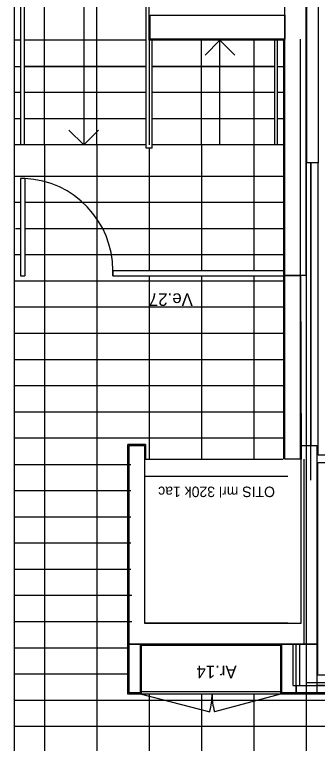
# Model space of a CAD drawing. Extents: x 1248 to 1356, y -443 to -224.
# Drawn here: x 1296.63 to 1299.52, y -237.59 to -230.63 of the extents above; entities that cross this region are included whole.
import ezdxf

# ---------------------------------------------------------------- set-up
doc = ezdxf.new("R2010")
doc.units = 0
for name, color, linetype in [('corte', 7, 'Continuous'), ('estereoctomias', 7, 'Continuous'), ('Level 1', 7, 'Continuous'), ('Level 10', 7, 'Continuous'), ('Level 13', 7, 'Continuous'), ('Level 2', 7, 'Continuous'), ('Level 3', 7, 'Continuous'), ('Level 40', 7, 'Continuous'), ('revestimentos', 7, 'Continuous'), ('vermelhos-cont', 7, 'Continuous')]:
    doc.layers.add(name, color=color, linetype=linetype)

msp = doc.modelspace()

# ---------------------------------------------------------------- linework, layer by layer
at = {"layer": 'corte'}
for p, q in [((1299.4204, -228.5639), (1299.4204, -232.0439)), ((1299.2133, -234.874), (1299.2133, -230.864)), ((1299.3633, -234.874), (1299.3633, -230.864)), ((1299.5304, -232.044), (1299.4204, -232.044)), ((1299.4604, -235.0752), (1299.4604, -232.044)), ((1297.834, -236.639), (1299.3933, -236.639)), ((1299.2908, -237.0363), (1299.9204, -237.0363)), ((1299.9904, -237.1063), (1299.1808, -237.1063)), ((1299.519, -237.1063), (1299.3208, -237.1063))]:
    msp.add_line(p, q, dxfattribs=at)
for points in [[(1299.4133, -233.1214), (1299.2133, -233.1214), (1299.2133, -228.5639), (1299.4133, -228.5639)], [(1299.519, -234.744), (1299.519, -236.639), (1297.724, -236.639), (1297.724, -234.744), (1297.874, -234.744), (1297.874, -236.439), (1299.369, -236.439), (1299.369, -234.744)]]:
    msp.add_lwpolyline(points, close=True, dxfattribs=at)
msp.add_lwpolyline([(1299.3208, -237.1063), (1299.3208, -236.639), (1299.519, -236.639), (1299.519, -237.1063)], dxfattribs=at)
at = {"layer": 'estereoctomias'}
for points in [[(1299.5304, -232.044), (1299.4204, -232.044), (1299.4204, -228.5639), (1299.2133, -228.5639), (1299.2133, -228.434), (1299.5304, -228.434)], [(1299.2133, -230.634), (1299.2133, -230.864), (1297.9283, -230.864), (1297.9283, -230.634)], [(1299.5304, -232.044), (1299.4604, -232.044), (1299.4604, -234.744), (1299.519, -234.744), (1299.519, -237.0059), (1299.9204, -237.0059), (1299.9204, -237.0363), (1299.519, -237.0363), (1299.519, -237.1047), (1299.519, -237.1063), (1299.9857, -237.1063), (1299.9904, -237.1063), (1299.9904, -236.9359), (1299.5297, -236.9359), (1299.5297, -234.9052), (1299.9329, -234.9052), (1299.9404, -234.9052), (1299.9404, -234.8352), (1299.5304, -234.8352)], [(1299.3633, -233.1214), (1299.369, -234.874), (1299.2133, -234.874), (1299.2133, -233.1214)], [(1297.834, -236.639), (1297.834, -237.1063), (1297.724, -237.1063), (1297.724, -236.639)], [(1299.2908, -236.639), (1299.2908, -237.0363), (1299.3208, -237.0363), (1299.3208, -237.1063), (1299.1808, -237.1063), (1299.1808, -236.639)]]:
    msp.add_lwpolyline(points, close=True, dxfattribs=at)
at = {"layer": 'Level 1'}
for p, q in [((1299.2133, -230.634), (1299.2133, -228.434)), ((1297.9283, -230.634), (1299.2133, -230.634)), ((1297.9283, -230.864), (1297.9283, -230.634)), ((1299.2133, -230.864), (1297.9283, -230.864)), ((1297.724, -234.744), (1297.724, -237.1063)), ((1297.8733, -234.744), (1297.7633, -234.744)), ((1299.369, -234.874), (1299.2133, -234.874)), ((1299.3933, -234.874), (1299.3933, -236.639)), ((1299.2433, -236.439), (1297.8733, -236.439)), ((1297.834, -237.1063), (1297.834, -236.639)), ((1299.1808, -236.639), (1299.1808, -237.1063)), ((1299.2908, -236.639), (1299.2908, -237.0363)), ((1299.3533, -236.639), (1299.3533, -237.0363)), ((1299.4204, -237.0059), (1299.9204, -237.0059)), ((1297.724, -237.1063), (1297.834, -237.1063))]:
    msp.add_line(p, q, dxfattribs=at)
at = {"layer": 'Level 10'}
for p, q in [((1296.9183, -231.874), (1296.9183, -230.124)), ((1297.4183, -231.874), (1297.4183, -230.124)), ((1296.6933, -230.874), (1296.6333, -230.874)), ((1297.8883, -230.874), (1296.7233, -230.874)), ((1298.4183, -231.874), (1298.4183, -230.874)), ((1298.9183, -230.874), (1298.9183, -231.874)), ((1296.6333, -231.124), (1296.6933, -231.124)), ((1296.7233, -231.124), (1297.8883, -231.124)), ((1297.9483, -231.124), (1299.1133, -231.124)), ((1299.1433, -231.124), (1299.2033, -231.124)), ((1296.6933, -231.374), (1296.6333, -231.374)), ((1297.8883, -231.374), (1296.7233, -231.374)), ((1299.1133, -231.374), (1297.9483, -231.374)), ((1299.2033, -231.374), (1299.1433, -231.374)), ((1296.6933, -231.624), (1296.6333, -231.624)), ((1297.8883, -231.624), (1296.7233, -231.624)), ((1299.1133, -231.624), (1297.9483, -231.624)), ((1299.2033, -231.624), (1299.1433, -231.624)), ((1297.8883, -231.874), (1296.6333, -231.874)), ((1296.9183, -231.874), (1296.9183, -239.074)), ((1297.4183, -231.874), (1297.4183, -239.074)), ((1299.1933, -231.874), (1297.9483, -231.874)), ((1298.4183, -231.874), (1298.4183, -233.074)), ((1298.9183, -231.874), (1298.9183, -233.074)), ((1297.9183, -231.904), (1297.9183, -233.074)), ((1299.2033, -232.174), (1296.6333, -232.174)), ((1296.6909, -232.424), (1296.6333, -232.424)), ((1299.1933, -232.424), (1296.7309, -232.424)), ((1296.6909, -232.674), (1296.6433, -232.674)), ((1299.2033, -232.674), (1296.7309, -232.674)), ((1296.6909, -232.924), (1296.6333, -232.924)), ((1299.2033, -232.924), (1296.7309, -232.924)), ((1297.9183, -233.124), (1297.9183, -234.874)), ((1298.4183, -233.124), (1298.4183, -234.874)), ((1298.9183, -233.124), (1298.9183, -234.874)), ((1299.2033, -233.174), (1296.6333, -233.174)), ((1299.2033, -233.424), (1296.6333, -233.424)), ((1299.2033, -233.674), (1296.6333, -233.674)), ((1299.2033, -233.924), (1296.6333, -233.924)), ((1299.2033, -234.174), (1296.6333, -234.174)), ((1299.2033, -234.424), (1296.6333, -234.424)), ((1299.2033, -234.674), (1296.6333, -234.674)), ((1296.6333, -234.924), (1297.7433, -234.924)), ((1297.874, -234.874), (1299.1933, -234.874)), ((1296.6333, -235.174), (1297.7433, -235.174)), ((1296.6333, -235.424), (1297.7433, -235.424)), ((1296.6333, -235.674), (1297.7433, -235.674)), ((1296.6333, -235.924), (1297.7433, -235.924)), ((1296.6333, -236.174), (1297.7533, -236.174)), ((1296.6333, -236.424), (1297.7533, -236.424)), ((1296.6333, -236.674), (1297.714, -236.674)), ((1296.6333, -236.924), (1297.714, -236.924)), ((1297.9183, -237.1163), (1297.9183, -239.074)), ((1298.4183, -237.1163), (1298.4183, -239.074)), ((1298.9183, -237.1163), (1298.9183, -239.074)), ((1299.4183, -237.1163), (1299.4183, -237.5021)), ((1299.4183, -237.1163), (1299.4183, -238.7163)), ((1296.6333, -237.174), (1299.1933, -237.174)), ((1296.6633, -237.174), (1299.9704, -237.174)), ((1296.6333, -237.424), (1299.1933, -237.424)), ((1296.6633, -237.424), (1318.1944, -237.424))]:
    msp.add_line(p, q, dxfattribs=at)
at = {"layer": 'Level 13'}
for p, q in [((1299.1708, -237.0963), (1297.844, -237.0963)), ((1299.1708, -237.1163), (1297.844, -237.1163))]:
    msp.add_line(p, q, dxfattribs=at)
at = {"layer": 'Level 2'}
for p, q in [((1296.6933, -231.874), (1296.6933, -230.124)), ((1296.7233, -230.124), (1296.7233, -231.874)), ((1297.2933, -230.124), (1297.2933, -231.874)), ((1297.8883, -231.904), (1297.8883, -230.094)), ((1297.9183, -230.874), (1297.9183, -230.124)), ((1297.8883, -230.874), (1296.7233, -230.874)), ((1297.9183, -230.874), (1297.9183, -231.874)), ((1297.9483, -231.904), (1297.9483, -230.874)), ((1298.4519, -231.0154), (1298.5933, -230.874)), ((1298.5933, -231.874), (1298.5933, -230.874)), ((1298.7347, -231.0154), (1298.5933, -230.874)), ((1299.1133, -230.874), (1299.1133, -231.874)), ((1299.1433, -231.874), (1299.1433, -230.874)), ((1297.8883, -231.124), (1296.7233, -231.124)), ((1299.1133, -231.124), (1297.9483, -231.124)), ((1297.8883, -231.374), (1296.7233, -231.374)), ((1299.1133, -231.374), (1297.9483, -231.374)), ((1297.8883, -231.624), (1296.7233, -231.624)), ((1299.1133, -231.624), (1297.9483, -231.624)), ((1297.1519, -231.7326), (1297.2933, -231.874)), ((1297.4347, -231.7326), (1297.2933, -231.874)), ((1297.8883, -231.874), (1296.6333, -231.874)), ((1299.2033, -231.874), (1297.9483, -231.874)), ((1297.9483, -231.904), (1297.8883, -231.904)), ((1296.6909, -232.1944), (1296.6909, -233.124)), ((1296.7309, -232.1944), (1296.6909, -232.1944)), ((1296.7309, -232.1944), (1296.7309, -233.124)), ((1296.6909, -233.124), (1296.7309, -233.124)), ((1297.5714, -233.124), (1297.5714, -233.074)), ((1297.5714, -233.074), (1297.5714, -233.124)), ((1297.5714, -233.074), (1299.2033, -233.074)), ((1297.5714, -233.124), (1299.2033, -233.124)), ((1299.2433, -235.039), (1297.8733, -235.039))]:
    msp.add_line(p, q, dxfattribs=at)
at = {"layer": 'Level 3'}
for p, q in [((1297.844, -237.1163), (1298.4964, -237.2849)), ((1299.1708, -237.1163), (1298.5409, -237.2849))]:
    msp.add_line(p, q, dxfattribs=at)
for centre, radius, start, end in [((1296.6909, -233.074), 0.8805, 0.00005, 87.39623), ((1297.8686, -237.1163), 0.65, 344.96553, 0), ((1299.1686, -237.1163), 0.65, 180, 195.03447)]:
    msp.add_arc(centre, radius, start, end, dxfattribs=at)
at = {"layer": 'revestimentos'}
for p, q in [((1296.6333, -239.074), (1296.6333, -228.774)), ((1297.9183, -230.874), (1297.9183, -230.624)), ((1299.2033, -230.874), (1297.9183, -230.874)), ((1299.2033, -234.874), (1299.2033, -230.874)), ((1297.714, -237.1163), (1297.714, -234.734)), ((1297.884, -234.734), (1297.714, -234.734)), ((1297.884, -234.734), (1297.884, -234.874)), ((1297.844, -236.649), (1299.1708, -236.649)), ((1297.844, -237.1163), (1297.844, -236.649)), ((1299.1708, -236.649), (1299.1708, -237.1163)), ((1297.844, -237.1163), (1297.714, -237.1163)), ((1299.9904, -237.1163), (1299.1708, -237.1163))]:
    msp.add_line(p, q, dxfattribs=at)
at = {"layer": 'vermelhos-cont'}
msp.add_line((1299.4199, -250.7923), (1299.4199, -225.5674), dxfattribs=at)

# ---------------------------------------------------------------- texts
at = {"layer": 'Level 1'}
msp.add_text('OTIS mrl 320k 1ac', height=0.1, rotation=180, dxfattribs=at).set_placement((1299.1189, -235.1359))
at = {"layer": 'Level 40'}
for s, p in [('Ve.27', (1298.335, -233.291)), ('Ar.14', (1298.7534, -236.8451))]:
    msp.add_text(s, height=0.12, rotation=180.00001, dxfattribs=at).set_placement(p)

doc.saveas('drawing.dxf')
